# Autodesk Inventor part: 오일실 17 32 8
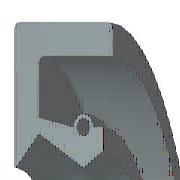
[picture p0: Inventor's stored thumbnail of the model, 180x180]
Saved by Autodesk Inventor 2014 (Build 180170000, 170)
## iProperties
IsCustomPart: 1
Created: 2012-02
Part Number: 오일실 17 32 8
Material: 고무
Description: 오일-실
Document SubType Name: Modeling
Standard: KS B 2804
Designer: mduedu
Standards Organization: KS
Language: ko-KR
Size Designation: D - 17 32 8
Categories: <MemberInstance><Categories><Category DisplayName="샤프트 부품" InternalName="7f7aeb1f-a693-4053-b835-cee3144e0d98" Mnemonic="SHFT"><Category DisplayName="실링" Intern
Density: 0.93 g/cm^3
Appearance: Rubber - Black - Version 1.1
Mass: 2.28027 g
Surface Area: 32.1224 cm^2
Volume: 2.45191 cm^3
Author: mduedu
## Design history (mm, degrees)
revolve "본체" stored, may be unused: angle "d17" = 90 deg
revolve "스프링1" stored, may be unused: angle "d18" = 90 deg
body "Solid1"
sketch "스케치1"
  geometry: L1 (0, 16)-(8, 16); L2 (8, 14.25)-(1.75, 14.25); L3 (1.75, 10.25)-(4.9, 8.5); L4 (4.9, 8.5)-(0, 8.5); L5 (0, 0)-(9.586, 0) reference; L6 (4.9, 8.5)-(6.3, 9.375); L7 (0, 18)-(0, -3) reference; L8 (-1.941, 0)-(11.507, 0) reference; L9 (4.2, 10.6)-(1.75, 11.21); L10 (1.75, 11.21)-(1.75, 14.25); L11 (0, 16)-(0, 8.588); L12 (4.9, 8.5)-(0, 8.5); L13 (1.75, 10.25)-(0.152, 8.528); L14 (8, 16)-(8, 14.25); L15 (5.6, 10.6)-(6.3, 10.6); L16 (6.3, 10.6)-(6.3, 9.375); C1 r 0.455 at (4.9, 10.6); A1 r 0.7 centre (4.9, 10.6) between (5.6, 10.6) and (4.2, 10.6); A2 r 0.088 centre (0.088, 8.588) between (0, 8.588) and (0.152, 8.528); 1 further point
  constraints: 28 end point, 5 horizontal alignment, 5 point on line, 4 point on circle, 4 vertical alignment, 3 centre point, 3 tangent, 2 collinear, 2 horizontal, 2 perpendicular, 1 coincident, 1 parallel
  dimensions: "d0" = 32 diameter of L1 L5 (= SD2); "d1" = 1.75 distance of L1.end L2.start (= SD); "d2" = 0.91 diameter of C1 (= SPDI); "d3" = 1.4 diameter of A1 (= SPDA); "d4" = 17 diameter of L3.end L5 (= NND); "d5" = 20.5 diameter of L3.start L5 (= TKDM); "d7" = 22.42 diameter of L9.end L5 (= TKDM + 0.24 x SWDT); "d8" = 1.75 distance between parallel lines of L11 L10 (= SD); "d9" = 4.9 distance from line of L11 C1.centre (= SPDST); "d10" = 21.2 diameter of C1.centre L5 (= HLDM); "d11" = 0.0875 radius of A2 (= 0.25 x LAB); "d12" = 6.3 distance between parallel lines of L11 L16 (= SDI); "d13" = 18.75 diameter of L6.end L5 (= ABDM); "d14" = 8 distance from line of L11 L1.end (= SWDT)
fillet "모깎기1" dims "d6" = 0.3 (= RR)
other parameters: "SD2" = 32 [user parameter; used in 1 equation term], "SWDT" = 8 [user parameter; used in 2 equation terms], "RR" = 0.3 [user parameter; used in 1 equation term], "SD" = 1.75 [user parameter; used in 2 equation terms], "NND" = 17 [user parameter; used in 1 equation term], "SPDA" = 1.4 [user parameter; used in 1 equation term], "SPDI" = 0.91 [user parameter; used in 1 equation term], "TKDM" = 20.5 [user parameter; used in 2 equation terms], "HLDM" = 21.2 [user parameter; used in 1 equation term], "ABDM" = 18.75 [user parameter; used in 1 equation term], "SDI" = 6.3 [user parameter; used in 1 equation term], "SPDST" = 4.9 [user parameter; used in 1 equation term], "LAB" = 0.35 [user parameter; used in 1 equation term], "d15" = 0, "d16" = 0, "d19" = 0
